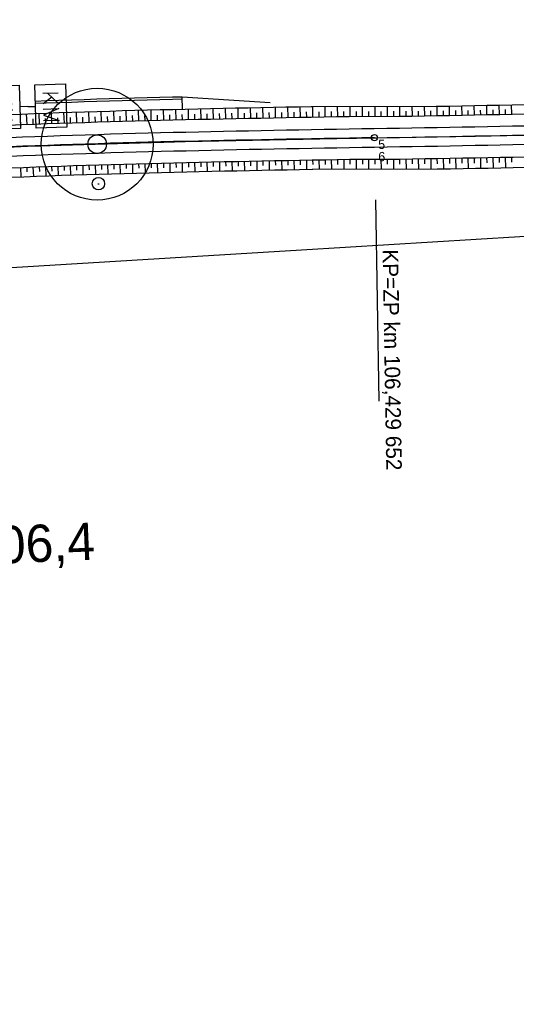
# Model space of a CAD drawing. Extents: x -759005 to -757278, y -1175311 to -1173953.
# Drawn here: x -758207.5 to -758167.6, y -1174834.3 to -1174754.3 of the extents above; entities that cross this region are included whole.
import ezdxf

# ---------------------------------------------------------------- set-up
doc = ezdxf.new("R2010")
doc.units = 0
for name, color, linetype in [('_NOR-návrh tenká', 7, 'Continuous'), ('_NOR-osa', 7, 'Continuous'), ('_NOR-popis', 7, 'Continuous'), ('_NOR-svahy', 7, 'Continuous'), ('_NOR-vytyčení', 7, 'Continuous'), ('G_Obvod stavby', 7, 'Continuous'), ('Vrstva 1', 7, 'Continuous'), ('Vrstva 7', 7, 'Continuous')]:
    doc.layers.add(name, color=color, linetype=linetype)

# ---------------------------------------------------------------- blocks, each defined once
blk = doc.blocks.new('C093_1')
at = {"layer": 'Vrstva 7'}
blk.add_line((-0.05, 0), (0.05, 0), dxfattribs=at)
blk.add_circle((0, 0), 0.5, dxfattribs=at)
blk = doc.blocks.new('C513_1')
at = {"layer": 'Vrstva 7'}
blk.add_circle((0, 0), 0.75, dxfattribs=at)
blk = doc.blocks.new('C020')
at = {"layer": 'Vrstva 7'}
for p, q in [((-1.017, 2.489), (-1.017, 1.242)), ((-0.182, 2.489), (-1.017, 1.654)), ((-0.713, 1.959), (-0.182, 1.242)), ((0, 0), (0, 0.623))]:
    blk.add_line(p, q, dxfattribs=at)
blk.add_lwpolyline([(-1.742, 0.623), (-1.742, 3.106), (1.746, 3.106), (1.746, 0.623)], close=True, dxfattribs=at)
blk.add_lwpolyline([(0.23, 1.242), (0.23, 2.489), (0.711, 1.242), (1.182, 2.489), (1.182, 1.242)], dxfattribs=at)
blk = doc.blocks.new('POINT_DISPLAY')
blk.add_line((0, 0), (0, 0))

msp = doc.modelspace()

# ---------------------------------------------------------------- linework, layer by layer
at = {"layer": '_NOR-návrh tenká'}
for p, q in [((-758194.43, -1174761.512), (-758194.453, -1174760.512)), ((-758194.453, -1174760.512), (-758187.38, -1174760.969))]:
    msp.add_line(p, q, dxfattribs=at)
for points in [[(-758208.404, -1174761.945), (-758207.39, -1174761.905), (-758206.376, -1174761.866), (-758205.362, -1174761.829), (-758204.349, -1174761.793), (-758203.335, -1174761.759), (-758202.321, -1174761.727), (-758201.308, -1174761.695), (-758200.294, -1174761.665), (-758199.281, -1174761.636), (-758198.268, -1174761.608), (-758197.255, -1174761.581), (-758196.242, -1174761.555), (-758195.229, -1174761.53), (-758194.216, -1174761.507), (-758193.204, -1174761.483), (-758192.191, -1174761.461), (-758191.179, -1174761.44), (-758190.167, -1174761.419), (-758189.154, -1174761.398), (-758188.143, -1174761.379), (-758187.131, -1174761.36), (-758186.119, -1174761.341), (-758185.108, -1174761.322), (-758184.096, -1174761.304), (-758184.038, -1174761.303), (-758174.039, -1174761.282), (-758173.987, -1174761.281), (-758172.977, -1174761.263), (-758171.968, -1174761.245), (-758170.958, -1174761.226), (-758169.949, -1174761.207), (-758168.94, -1174761.187), (-758167.93, -1174761.167), (-758166.921, -1174761.146)], [(-758206.238, -1174760.86), (-758205.398, -1174760.83), (-758204.383, -1174760.794), (-758203.368, -1174760.76), (-758202.353, -1174760.727), (-758201.338, -1174760.696), (-758200.324, -1174760.665), (-758199.309, -1174760.636), (-758198.295, -1174760.608), (-758197.281, -1174760.581), (-758196.267, -1174760.556), (-758195.253, -1174760.531), (-758194.453, -1174760.512)], [(-758206.233, -1174761.04), (-758205.392, -1174761.009), (-758204.377, -1174760.974), (-758203.362, -1174760.94), (-758202.347, -1174760.907), (-758201.333, -1174760.875), (-758200.318, -1174760.845), (-758199.304, -1174760.816), (-758198.29, -1174760.788), (-758197.276, -1174760.761), (-758196.262, -1174760.736), (-758195.249, -1174760.711), (-758194.449, -1174760.692)], [(-758208.37, -1174762.794), (-758207.357, -1174762.754), (-758206.345, -1174762.715), (-758205.332, -1174762.678), (-758204.319, -1174762.643), (-758203.307, -1174762.609), (-758202.294, -1174762.576), (-758201.282, -1174762.545), (-758200.269, -1174762.514), (-758199.257, -1174762.485), (-758198.245, -1174762.458), (-758197.233, -1174762.431), (-758196.221, -1174762.405), (-758195.208, -1174762.38), (-758194.196, -1174762.356), (-758193.185, -1174762.333), (-758192.173, -1174762.311), (-758191.161, -1174762.289), (-758190.149, -1174762.269), (-758189.138, -1174762.248), (-758188.126, -1174762.229), (-758187.115, -1174762.209), (-758186.103, -1174762.191), (-758185.092, -1174762.172), (-758184.081, -1174762.154), (-758183.07, -1174762.137), (-758182.059, -1174762.119), (-758181.048, -1174762.102), (-758181.026, -1174762.101), (-758177.026, -1174762.084), (-758177.005, -1174762.083), (-758175.995, -1174762.066), (-758174.984, -1174762.048), (-758173.974, -1174762.031), (-758172.964, -1174762.013), (-758171.954, -1174761.994), (-758170.944, -1174761.976), (-758169.934, -1174761.957), (-758168.925, -1174761.937), (-758167.915, -1174761.917), (-758166.906, -1174761.896)], [(-758208.33, -1174763.793), (-758207.319, -1174763.753), (-758206.308, -1174763.715), (-758205.296, -1174763.678), (-758204.285, -1174763.642), (-758203.274, -1174763.608), (-758202.263, -1174763.576), (-758201.251, -1174763.544), (-758200.24, -1174763.514), (-758199.229, -1174763.485), (-758198.218, -1174763.457), (-758197.207, -1174763.43), (-758196.196, -1174763.405), (-758195.184, -1174763.38), (-758194.173, -1174763.356), (-758193.162, -1174763.333), (-758192.151, -1174763.311), (-758191.14, -1174763.289), (-758190.129, -1174763.268), (-758189.118, -1174763.248), (-758188.107, -1174763.228), (-758187.096, -1174763.209), (-758186.085, -1174763.191), (-758185.074, -1174763.172), (-758184.063, -1174763.154), (-758183.053, -1174763.137), (-758182.042, -1174763.119), (-758181.031, -1174763.102), (-758180.021, -1174763.085), (-758179.01, -1174763.067), (-758177.999, -1174763.05), (-758176.989, -1174763.033), (-758175.978, -1174763.016), (-758174.968, -1174762.998), (-758173.957, -1174762.981), (-758172.947, -1174762.963), (-758171.937, -1174762.944), (-758170.926, -1174762.926), (-758169.916, -1174762.906), (-758168.906, -1174762.887), (-758167.896, -1174762.866), (-758166.886, -1174762.846)], [(-758208.269, -1174765.292), (-758207.261, -1174765.252), (-758206.252, -1174765.214), (-758205.243, -1174765.177), (-758204.234, -1174765.141), (-758203.224, -1174765.107), (-758202.215, -1174765.075), (-758201.206, -1174765.044), (-758200.196, -1174765.013), (-758199.187, -1174764.985), (-758198.177, -1174764.957), (-758197.168, -1174764.93), (-758196.158, -1174764.904), (-758195.148, -1174764.879), (-758194.138, -1174764.856), (-758193.129, -1174764.833), (-758192.119, -1174764.81), (-758191.109, -1174764.789), (-758190.098, -1174764.768), (-758189.088, -1174764.748), (-758188.078, -1174764.728), (-758187.068, -1174764.709), (-758186.058, -1174764.69), (-758185.047, -1174764.672), (-758184.037, -1174764.654), (-758183.027, -1174764.636), (-758182.016, -1174764.619), (-758181.006, -1174764.602), (-758179.995, -1174764.584), (-758178.984, -1174764.567), (-758177.974, -1174764.55), (-758176.963, -1174764.533), (-758175.952, -1174764.516), (-758174.942, -1174764.498), (-758173.931, -1174764.48), (-758172.92, -1174764.462), (-758171.909, -1174764.444), (-758170.898, -1174764.425), (-758169.887, -1174764.406), (-758168.876, -1174764.386), (-758167.865, -1174764.366), (-758166.854, -1174764.345)], [(-758208.231, -1174766.241), (-758207.224, -1174766.201), (-758206.216, -1174766.163), (-758205.209, -1174766.126), (-758204.201, -1174766.091), (-758203.193, -1174766.057), (-758202.185, -1174766.024), (-758201.177, -1174765.993), (-758200.169, -1174765.963), (-758199.16, -1174765.934), (-758198.152, -1174765.906), (-758197.143, -1174765.88), (-758196.134, -1174765.854), (-758195.125, -1174765.829), (-758194.116, -1174765.805), (-758193.107, -1174765.782), (-758192.098, -1174765.76), (-758191.089, -1174765.739), (-758190.079, -1174765.718), (-758189.07, -1174765.698), (-758188.06, -1174765.678), (-758187.05, -1174765.659), (-758186.04, -1174765.64), (-758185.03, -1174765.622), (-758184.02, -1174765.604), (-758183.01, -1174765.586), (-758182, -1174765.569), (-758180.989, -1174765.551), (-758180.968, -1174765.551), (-758176.968, -1174765.533), (-758176.946, -1174765.533), (-758175.935, -1174765.515), (-758174.924, -1174765.498), (-758173.913, -1174765.48), (-758172.902, -1174765.462), (-758171.891, -1174765.444), (-758170.879, -1174765.425), (-758169.868, -1174765.406), (-758168.857, -1174765.386), (-758167.845, -1174765.366), (-758166.833, -1174765.345)], [(-758208.201, -1174766.991), (-758207.195, -1174766.951), (-758206.188, -1174766.912), (-758205.182, -1174766.876), (-758204.175, -1174766.84), (-758203.168, -1174766.807), (-758202.161, -1174766.774), (-758201.154, -1174766.743), (-758200.147, -1174766.713), (-758199.139, -1174766.684), (-758198.131, -1174766.656), (-758197.124, -1174766.629), (-758196.116, -1174766.604), (-758195.107, -1174766.579), (-758194.099, -1174766.555), (-758193.09, -1174766.532), (-758192.082, -1174766.51), (-758191.073, -1174766.488), (-758190.064, -1174766.468), (-758189.055, -1174766.447), (-758188.046, -1174766.428), (-758187.036, -1174766.409), (-758186.027, -1174766.39), (-758185.017, -1174766.372), (-758184.007, -1174766.354), (-758183.955, -1174766.353), (-758173.956, -1174766.331), (-758173.898, -1174766.33), (-758172.887, -1174766.312), (-758171.875, -1174766.294), (-758170.864, -1174766.275), (-758169.852, -1174766.256), (-758168.84, -1174766.236), (-758167.828, -1174766.216), (-758166.815, -1174766.195)]]:
    msp.add_lwpolyline(points, dxfattribs=at)
at = {"layer": '_NOR-osa'}
for points in [[(-758178.997, -1174763.817), (-758177.987, -1174763.8), (-758176.976, -1174763.783), (-758175.965, -1174763.766), (-758174.955, -1174763.748), (-758173.944, -1174763.73), (-758172.933, -1174763.712), (-758171.923, -1174763.694), (-758170.912, -1174763.675), (-758169.902, -1174763.656), (-758168.891, -1174763.637), (-758167.881, -1174763.616), (-758166.87, -1174763.595)], [(-758178.997, -1174763.817), (-758180.008, -1174763.834), (-758181.018, -1174763.852), (-758182.029, -1174763.869), (-758183.04, -1174763.886), (-758184.05, -1174763.904), (-758185.061, -1174763.922), (-758186.071, -1174763.94), (-758187.082, -1174763.959), (-758188.093, -1174763.978), (-758189.103, -1174763.998), (-758190.114, -1174764.018), (-758191.124, -1174764.039), (-758192.135, -1174764.061), (-758193.145, -1174764.083), (-758194.156, -1174764.106), (-758195.166, -1174764.13), (-758196.177, -1174764.154), (-758197.187, -1174764.18), (-758198.198, -1174764.207), (-758199.208, -1174764.235), (-758200.218, -1174764.264), (-758201.229, -1174764.294), (-758202.239, -1174764.325), (-758203.249, -1174764.358), (-758204.259, -1174764.392), (-758205.269, -1174764.427), (-758206.28, -1174764.464), (-758207.29, -1174764.503), (-758208.3, -1174764.543)]]:
    msp.add_lwpolyline(points, dxfattribs=at)
msp.add_circle((-758178.997, -1174763.817), 0.25, dxfattribs=at)
msp.add_circle((-758178.997, -1174763.817), 0.25, dxfattribs=at)
at = {"layer": '_NOR-popis'}
msp.add_line((-758178.912, -1174768.817), (-758178.638, -1174785.011), dxfattribs=at)
at = {"layer": '_NOR-svahy'}
for points in [[(-758170.951, -1174761.976), (-758170.965, -1174761.226)], [(-758169.951, -1174761.957), (-758169.965, -1174761.207)], [(-758168.951, -1174761.937), (-758168.966, -1174761.188)], [(-758167.951, -1174761.917), (-758167.966, -1174761.168)], [(-758206.941, -1174762.738), (-758206.974, -1174761.889)], [(-758205.942, -1174762.701), (-758205.973, -1174761.851)], [(-758204.943, -1174762.665), (-758204.973, -1174761.815)], [(-758203.943, -1174762.63), (-758203.972, -1174761.781)], [(-758202.944, -1174762.597), (-758202.971, -1174761.748)], [(-758201.944, -1174762.565), (-758201.971, -1174761.716)], [(-758200.945, -1174762.535), (-758200.97, -1174761.685)], [(-758199.945, -1174762.505), (-758199.97, -1174761.656)], [(-758198.946, -1174762.477), (-758198.969, -1174761.627)], [(-758197.946, -1174762.45), (-758197.969, -1174761.6)], [(-758197.446, -1174762.436), (-758197.457, -1174762.012)], [(-758196.946, -1174762.424), (-758196.968, -1174761.574)], [(-758196.447, -1174762.411), (-758196.457, -1174761.986)], [(-758195.947, -1174762.398), (-758195.968, -1174761.549)], [(-758195.447, -1174762.386), (-758195.457, -1174761.961)], [(-758194.947, -1174762.374), (-758194.967, -1174761.524)], [(-758194.447, -1174762.362), (-758194.457, -1174761.937)], [(-758193.947, -1174762.351), (-758193.967, -1174761.501)], [(-758193.447, -1174762.339), (-758193.457, -1174761.914)], [(-758192.948, -1174762.328), (-758192.966, -1174761.478)], [(-758192.448, -1174762.317), (-758192.457, -1174761.892)], [(-758191.948, -1174762.306), (-758191.966, -1174761.456)], [(-758191.448, -1174762.296), (-758191.457, -1174761.871)], [(-758190.948, -1174762.285), (-758190.966, -1174761.435)], [(-758190.448, -1174762.275), (-758190.457, -1174761.85)], [(-758189.948, -1174762.264), (-758189.965, -1174761.415)], [(-758189.448, -1174762.254), (-758189.457, -1174761.83)], [(-758188.948, -1174762.245), (-758188.965, -1174761.395)], [(-758188.449, -1174762.235), (-758188.457, -1174761.81)], [(-758187.949, -1174762.225), (-758187.965, -1174761.375)], [(-758187.449, -1174762.216), (-758187.457, -1174761.791)], [(-758186.949, -1174762.206), (-758186.965, -1174761.356)], [(-758186.449, -1174762.197), (-758186.457, -1174761.772)], [(-758185.949, -1174762.188), (-758185.964, -1174761.338)], [(-758185.449, -1174762.179), (-758185.457, -1174761.754)], [(-758184.949, -1174762.17), (-758184.964, -1174761.32)], [(-758184.449, -1174762.161), (-758184.457, -1174761.736)], [(-758183.949, -1174762.152), (-758183.964, -1174761.303)], [(-758183.449, -1174762.143), (-758183.457, -1174761.723)], [(-758182.949, -1174762.135), (-758182.964, -1174761.301)], [(-758182.449, -1174762.126), (-758182.457, -1174761.713)], [(-758181.95, -1174762.117), (-758181.964, -1174761.299)], [(-758181.45, -1174762.109), (-758181.457, -1174761.703)], [(-758180.95, -1174762.101), (-758180.953, -1174761.297)], [(-758180.45, -1174762.099), (-758180.452, -1174761.697)], [(-758179.95, -1174762.097), (-758179.953, -1174761.295)], [(-758179.45, -1174762.094), (-758179.452, -1174761.694)], [(-758178.95, -1174762.092), (-758178.953, -1174761.292)], [(-758178.45, -1174762.09), (-758178.452, -1174761.691)], [(-758177.95, -1174762.088), (-758177.953, -1174761.29)], [(-758177.45, -1174762.085), (-758177.452, -1174761.687)], [(-758176.95, -1174762.082), (-758176.963, -1174761.288)], [(-758176.45, -1174762.074), (-758176.457, -1174761.68)], [(-758175.95, -1174762.065), (-758175.963, -1174761.286)], [(-758175.45, -1174762.056), (-758175.457, -1174761.671)], [(-758174.95, -1174762.048), (-758174.963, -1174761.284)], [(-758174.45, -1174762.039), (-758174.457, -1174761.661)], [(-758173.95, -1174762.03), (-758173.964, -1174761.28)], [(-758173.45, -1174762.021), (-758173.457, -1174761.646)], [(-758172.95, -1174762.013), (-758172.964, -1174761.263)], [(-758172.45, -1174762.003), (-758172.457, -1174761.629)], [(-758171.951, -1174761.994), (-758171.964, -1174761.245)], [(-758171.451, -1174761.985), (-758171.458, -1174761.61)], [(-758170.451, -1174761.966), (-758170.458, -1174761.591)], [(-758169.451, -1174761.947), (-758169.458, -1174761.572)], [(-758168.451, -1174761.927), (-758168.459, -1174761.552)], [(-758207.441, -1174762.757), (-758207.458, -1174762.333)], [(-758206.442, -1174762.719), (-758206.458, -1174762.294)], [(-758205.442, -1174762.682), (-758205.458, -1174762.258)], [(-758204.443, -1174762.647), (-758204.458, -1174762.223)], [(-758203.444, -1174762.613), (-758203.458, -1174762.189)], [(-758202.444, -1174762.581), (-758202.458, -1174762.156)], [(-758201.445, -1174762.55), (-758201.458, -1174762.125)], [(-758200.445, -1174762.52), (-758200.458, -1174762.095)], [(-758199.445, -1174762.491), (-758199.458, -1174762.066)], [(-758198.446, -1174762.463), (-758198.458, -1174762.038)], [(-758202.466, -1174766.033), (-758202.442, -1174766.783)], [(-758201.966, -1174766.018), (-758201.955, -1174766.392)], [(-758201.467, -1174766.002), (-758201.443, -1174766.752)], [(-758200.967, -1174765.987), (-758200.956, -1174766.362)], [(-758200.467, -1174765.972), (-758200.445, -1174766.722)], [(-758199.967, -1174765.957), (-758199.957, -1174766.332)], [(-758199.468, -1174765.943), (-758199.446, -1174766.693)], [(-758198.968, -1174765.929), (-758198.957, -1174766.304)], [(-758198.468, -1174765.915), (-758198.447, -1174766.665)], [(-758197.968, -1174765.902), (-758197.958, -1174766.276)], [(-758197.468, -1174765.888), (-758197.448, -1174766.638)], [(-758196.968, -1174765.875), (-758196.959, -1174766.25)], [(-758196.469, -1174765.862), (-758196.45, -1174766.612)], [(-758195.969, -1174765.85), (-758195.96, -1174766.225)], [(-758195.469, -1174765.838), (-758195.451, -1174766.587)], [(-758194.969, -1174765.826), (-758194.96, -1174766.2)], [(-758194.469, -1174765.814), (-758194.452, -1174766.563)], [(-758193.969, -1174765.802), (-758193.961, -1174766.177)], [(-758193.469, -1174765.791), (-758193.452, -1174766.54)], [(-758192.97, -1174765.779), (-758192.961, -1174766.154)], [(-758192.47, -1174765.768), (-758192.453, -1174766.518)], [(-758191.97, -1174765.757), (-758191.962, -1174766.132)], [(-758191.47, -1174765.747), (-758191.454, -1174766.497)], [(-758190.97, -1174765.736), (-758190.962, -1174766.111)], [(-758190.47, -1174765.726), (-758190.455, -1174766.476)], [(-758189.97, -1174765.716), (-758189.963, -1174766.091)], [(-758189.47, -1174765.706), (-758189.455, -1174766.455)], [(-758188.97, -1174765.696), (-758188.963, -1174766.071)], [(-758188.471, -1174765.686), (-758188.456, -1174766.436)], [(-758187.971, -1174765.676), (-758187.964, -1174766.051)], [(-758187.471, -1174765.667), (-758187.457, -1174766.417)], [(-758186.971, -1174765.657), (-758186.964, -1174766.032)], [(-758186.471, -1174765.648), (-758186.457, -1174766.398)], [(-758185.971, -1174765.639), (-758185.964, -1174766.014)], [(-758185.471, -1174765.63), (-758185.458, -1174766.38)], [(-758184.971, -1174765.621), (-758184.965, -1174765.996)], [(-758184.471, -1174765.612), (-758184.458, -1174766.362)], [(-758183.971, -1174765.603), (-758183.965, -1174765.978)], [(-758183.471, -1174765.594), (-758183.458, -1174766.352)], [(-758182.972, -1174765.585), (-758182.965, -1174765.968)], [(-758182.472, -1174765.577), (-758182.458, -1174766.35)], [(-758181.972, -1174765.568), (-758181.965, -1174765.958)], [(-758181.472, -1174765.56), (-758181.458, -1174766.347)], [(-758180.972, -1174765.551), (-758180.965, -1174765.949)], [(-758180.472, -1174765.549), (-758180.468, -1174766.345)], [(-758179.972, -1174765.547), (-758179.97, -1174765.945)], [(-758179.472, -1174765.544), (-758179.468, -1174766.343)], [(-758178.972, -1174765.542), (-758178.97, -1174765.942)], [(-758178.472, -1174765.54), (-758178.468, -1174766.341)], [(-758177.972, -1174765.538), (-758177.97, -1174765.939)], [(-758177.472, -1174765.535), (-758177.468, -1174766.339)], [(-758176.972, -1174765.533), (-758176.97, -1174765.935)], [(-758176.472, -1174765.525), (-758176.458, -1174766.337)], [(-758175.972, -1174765.516), (-758175.965, -1174765.926)], [(-758175.472, -1174765.507), (-758175.458, -1174766.334)], [(-758174.972, -1174765.499), (-758174.965, -1174765.916)], [(-758174.472, -1174765.49), (-758174.457, -1174766.332)], [(-758173.972, -1174765.481), (-758173.965, -1174765.906)], [(-758173.472, -1174765.472), (-758173.457, -1174766.322)], [(-758172.972, -1174765.463), (-758172.965, -1174765.888)], [(-758172.473, -1174765.454), (-758172.457, -1174766.304)], [(-758171.973, -1174765.445), (-758171.965, -1174765.87)], [(-758171.473, -1174765.436), (-758171.457, -1174766.286)], [(-758170.973, -1174765.427), (-758170.965, -1174765.852)], [(-758170.473, -1174765.417), (-758170.457, -1174766.267)], [(-758169.973, -1174765.408), (-758169.965, -1174765.833)], [(-758169.473, -1174765.398), (-758169.457, -1174766.248)], [(-758168.973, -1174765.389), (-758168.965, -1174765.813)], [(-758168.473, -1174765.379), (-758168.456, -1174766.228)], [(-758167.973, -1174765.369), (-758167.965, -1174765.793)], [(-758207.463, -1174766.211), (-758207.433, -1174766.96)], [(-758206.963, -1174766.191), (-758206.949, -1174766.566)], [(-758206.464, -1174766.172), (-758206.435, -1174766.922)], [(-758205.964, -1174766.154), (-758205.95, -1174766.529)], [(-758205.464, -1174766.136), (-758205.437, -1174766.885)], [(-758204.965, -1174766.118), (-758204.952, -1174766.492)], [(-758204.465, -1174766.1), (-758204.439, -1174766.85)], [(-758203.965, -1174766.083), (-758203.953, -1174766.458)], [(-758203.466, -1174766.066), (-758203.44, -1174766.816)], [(-758202.966, -1174766.05), (-758202.954, -1174766.424)]]:
    msp.add_lwpolyline(points, dxfattribs=at)
at = {"layer": 'G_Obvod stavby'}
msp.add_lwpolyline([(-758392.72, -1174840.756), (-758391.23, -1174838.56), (-758368.37, -1174821.64), (-758340.31, -1174807.33), (-758320.27, -1174796.89), (-758301, -1174790.21), (-758267.96, -1174782.93), (-758224.96, -1174775.27), (-758184.87, -1174772.83), (-758142.71, -1174770.26), (-758089.84, -1174768.68), (-758106.02, -1174731.44), (-758149.09, -1174725.67), (-758199.62, -1174726.6), (-758225.76, -1174732.36), (-758252.17, -1174738.18), (-758254.97, -1174739.34), (-758266.58, -1174744.16), (-758279.45, -1174749.49), (-758302.42, -1174759.02), (-758331.68, -1174770.24), (-758367.17, -1174799.81), (-758405.64, -1174832.2)], dxfattribs=at)
at = {"layer": 'Vrstva 1'}
for points in [[(-758275.047, -1174773.289), (-758265.484, -1174771.118), (-758253.61, -1174768.888), (-758243.69, -1174767.426), (-758231.371, -1174766.042), (-758219.363, -1174765.122), (-758206.915, -1174764.505), (-758194.225, -1174764.118), (-758182.013, -1174763.871), (-758170.862, -1174763.683), (-758162.019, -1174763.496), (-758153.195, -1174763.228), (-758152.069, -1174763.19), (-758141.836, -1174762.716), (-758130.402, -1174761.933), (-758120.726, -1174760.981), (-758108.612, -1174759.398), (-758096.467, -1174757.277), (-758085.591, -1174754.917)], [(-758196.804, -1174764.197), (-758194.225, -1174764.118), (-758182.013, -1174763.871), (-758170.862, -1174763.683), (-758162.019, -1174763.496), (-758153.195, -1174763.228), (-758152.069, -1174763.19), (-758141.836, -1174762.716), (-758130.402, -1174761.933), (-758129.559, -1174761.85)], [(-758237.305, -1174766.709), (-758231.371, -1174766.042), (-758219.363, -1174765.122), (-758206.915, -1174764.505), (-758205.8, -1174764.471)]]:
    msp.add_lwpolyline(points, dxfattribs=at)
at = {"layer": 'Vrstva 7'}
msp.add_circle((-758201.302, -1174764.334), 4.5, dxfattribs=at)

# ---------------------------------------------------------------- block references
at = {"layer": '_NOR-vytyčení'}
msp.add_blockref('POINT_DISPLAY', (-758178.997, -1174763.817), dxfattribs=at)
msp.add_blockref('POINT_DISPLAY', (-758178.997, -1174763.817), dxfattribs=at)
at = {"layer": 'Vrstva 7'}
for name, p, rotation in [('C020', (-758206.89, -1174761.314), 91.74677671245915), ('C020', (-758206.89, -1174761.314), -88.25322328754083), ('C513_1', (-758201.302, -1174764.334), 1.7467767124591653), ('C093_1', (-758201.201, -1174767.514), 1.7467767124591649)]:
    msp.add_blockref(name, p, dxfattribs=dict(at, rotation=rotation))

# ---------------------------------------------------------------- texts
at = {"layer": '_NOR-popis'}
for s, height, rotation, p in [('KP=ZP km 106,429 652', 1.25, 270.97093, (-758178.345, -1174772.808)), ('106,4', 3, 2.3427, (-758211.462, -1174798.184))]:
    msp.add_text(s, height=height, rotation=rotation, dxfattribs=at).set_placement(p)
at = {"layer": '_NOR-vytyčení'}
for s, p in [('5', (-758178.697, -1174764.717)), ('6', (-758178.691, -1174765.708))]:
    msp.add_text(s, height=0.75, rotation=360, dxfattribs=at).set_placement(p)

doc.saveas('drawing.dxf')
